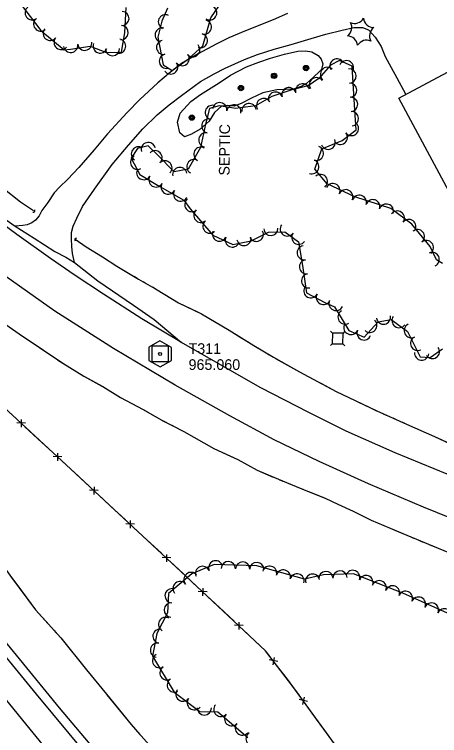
# Model space of a CAD drawing. Extents: x 353423 to 364002, y 127000 to 201942.
# Drawn here: x 358568 to 358806.9, y 133651.2 to 134056.7 of the extents above; entities that cross this region are included whole.
import ezdxf

# ---------------------------------------------------------------- set-up
doc = ezdxf.new("R2010")
doc.units = 0
for name, color, linetype in [('E_BMGRD', 7, 'Continuous'), ('E_DTM_SlopeBottom', 7, 'Continuous'), ('E_DTM_SlopeTop', 7, 'Continuous'), ('E_FEN_Generic', 7, 'Continuous'), ('E_MISCPROP', 7, 'Continuous'), ('E_SGN', 7, 'Continuous'), ('E_STRUCT_WingWall', 7, 'Continuous'), ('E_UTL_ETransformer', 7, 'Continuous'), ('E_WTR_FlowLine', 7, 'Continuous')]:
    doc.layers.add(name, color=color, linetype=linetype)

msp = doc.modelspace()

# ---------------------------------------------------------------- linework, layer by layer
at = {"layer": 'E_BMGRD'}
for points in [[(358643.46, 133869.57), (358643.46, 133862.18), (358649.92, 133858.46), (358656.31, 133862.12), (358656.31, 133869.45), (358649.79, 133873.17)], [(358645.37, 133861.31), (358645.37, 133870.31), (358654.37, 133870.31), (358654.37, 133861.31)]]:
    msp.add_lwpolyline(points, close=True, dxfattribs=at)
msp.add_circle((358649.87, 133865.81), 0.871, dxfattribs=at)
at = {"layer": 'E_DTM_SlopeBottom'}
for p, q in [((358571.92, 133824.67), (358572.02, 133828.9)), ((358574.25, 133826.94), (358569.32, 133827.08)), ((358594.71, 133808.03), (358589.78, 133808.17)), ((358592.38, 133805.76), (358592.48, 133809.99)), ((358615.13, 133789.07), (358610.2, 133789.23)), ((358612.8, 133786.81), (358612.91, 133791.04)), ((358633.19, 133767.83), (358633.3, 133772.06)), ((358635.52, 133770.09), (358630.59, 133770.25)), ((358655.92, 133751.11), (358650.99, 133751.27)), ((358653.59, 133748.85), (358653.7, 133753.08)), ((358676.28, 133732.08), (358671.35, 133732.26)), ((358673.94, 133729.83), (358674.07, 133734.06)), ((358694.26, 133710.77), (358694.39, 133715)), ((358696.6, 133713.02), (358691.67, 133713.2)), ((358713.34, 133690.93), (358714.16, 133695.07)), ((358716.02, 133692.76), (358711.18, 133693.74)), ((358732.73, 133670.42), (358727.93, 133671.53)), ((358730.01, 133668.66), (358730.94, 133672.78))]:
    msp.add_line(p, q, dxfattribs=at)
for points in [[(358836.43, 133525.4), (358796.03, 133580.43), (358760.79, 133628.75), (358724.55, 133678.75), (358709.17, 133698.85), (358664.38, 133740.86), (358599.77, 133800.98), (358519.01, 133875.61), (358455.91, 133934.64), (358435.86, 133952.59)], [(358569.08, 133829.34), (358560.77, 133837.02)], [(358581.23, 133818.11), (358573.92, 133824.87)], [(358589.54, 133810.43), (358581.23, 133818.11)], [(358601.69, 133799.2), (358599.77, 133800.98), (358594.38, 133805.96)], [(358609.97, 133791.49), (358601.69, 133799.2)], [(358622.08, 133780.22), (358614.79, 133787)], [(358630.37, 133772.51), (358622.08, 133780.22)], [(358642.48, 133761.24), (358635.19, 133768.02)], [(358650.76, 133753.53), (358642.48, 133761.24)], [(358662.87, 133742.26), (358655.58, 133749.04)], [(358671.13, 133734.52), (358664.38, 133740.86), (358662.87, 133742.26)], [(358683.2, 133723.21), (358675.93, 133730.02)], [(358691.45, 133715.46), (358683.2, 133723.21)], [(358703.52, 133704.15), (358696.26, 133710.96)], [(358711.34, 133696.01), (358709.17, 133698.85), (358703.52, 133704.15)], [(358721.39, 133682.88), (358715.34, 133690.78)], [(358728.14, 133673.79), (358724.55, 133678.75), (358721.39, 133682.88)], [(358737.85, 133660.4), (358732.01, 133668.46)], [(358744.49, 133651.23), (358737.85, 133660.4)]]:
    msp.add_lwpolyline(points, dxfattribs=at)
for centre, major_axis, ratio, start_param, end_param in [((358578.26, 133946.62), (1.1, -0.85), 0.731764, 5.356084, 7.210314), ((358603.23, 133929.74), (-1.27, 0.73), 0.674015, 5.356056, 7.210287)]:
    msp.add_ellipse(centre, major_axis=major_axis, ratio=ratio, start_param=start_param, end_param=end_param, dxfattribs=at)
at = {"layer": 'E_DTM_SlopeTop'}
for points in [[(358441.35, 134045.38), (358458.82, 134027.84), (358479.33, 134008.92), (358498.38, 133991.81), (358519.6, 133974.36), (358536.98, 133960.5), (358552.96, 133948.34), (358568.5, 133937.59), (358579.06, 133930.82), (358590.76, 133923.39), (358596.83, 133920.22), (358601.76, 133917.16), (358614.92, 133906.85), (358634.85, 133893.15), (358646.44, 133885.24), (358661.91, 133872.27)], [(358811.23, 133798.22), (358782.01, 133810.22), (358754.41, 133822.42), (358733.49, 133832.87), (358706.56, 133846.65), (358685.05, 133858.99), (358661.91, 133872.27), (358639.64, 133885.49), (358617.98, 133899.41), (358602.1, 133910), (358588.29, 133919.5), (358569.39, 133933.03), (358553.47, 133944.6), (358528.29, 133963.74), (358501.39, 133985.83), (358475.03, 134008.4), (358453.71, 134028.73), (358441, 134040.82)], [(358821.59, 133770.11), (358797.89, 133779.58), (358767.05, 133792.72), (358739.29, 133805.36), (358714.04, 133817.51), (358689, 133830.96), (358658.38, 133848.17), (358623.71, 133868.81), (358590.77, 133889.83), (358555.24, 133914.83), (358518.1, 133943.09), (358487.78, 133968.01), (358458.61, 133993.96), (358438.9, 134012.47)], [(358426.16, 133877.85), (358444.54, 133853.9), (358473.07, 133816.88), (358497.01, 133785.79), (358520.47, 133756.39), (358545.34, 133725.02), (358568.91, 133696.33), (358593.18, 133666.86), (358619.62, 133635.5), (358642.87, 133608.27), (358669.48, 133578.91), (358695.76, 133550.47), (358719.81, 133525.68)], [(358427.98, 133866.96), (358447.76, 133841.26), (358475.64, 133804.95), (358499.53, 133774.24), (358523.91, 133743.42), (358547.15, 133714.62), (358580.13, 133674.49), (358607.7, 133641.32), (358630.41, 133614.69), (358652.74, 133589.31), (358675.41, 133564.69), (358697.96, 133540.66), (358709.12, 133529.01)], [(358427.64, 133842.77), (358450.55, 133812.94), (358476.17, 133779.51), (358503.57, 133744.61), (358526.49, 133715.53), (358553.52, 133682.92), (358574.17, 133657.7), (358594.12, 133633.47), (358615.74, 133608.31), (358632.02, 133589.63), (358651.76, 133567.57), (358673.07, 133544.31), (358691.64, 133525.31)]]:
    msp.add_lwpolyline(points, dxfattribs=at)
at = {"layer": 'E_FEN_Generic'}
for points in [[(358568.39, 134066.85), (358582.85, 134047.75), (358595.93, 134036.77), (358599.52, 134037.17), (358610.55, 134038.88), (358619.81, 134035.34), (358628.08, 134035.48), (358630.04, 134046.33), (358630.85, 134060.61)], [(358654.07, 134060.2), (358650.78, 134053.02), (358648.58, 134043.93), (358651.61, 134028.38), (358656.7, 134025.27), (358665.74, 134031.84), (358673.79, 134039.08), (358678.35, 134054.76), (358685.24, 134065.18)], [(358808.53, 133916.57), (358805.2, 133918.67), (358801.72, 133926.29), (358791.4, 133938.77), (358779.49, 133947.5), (358759.3, 133954.09), (358743.71, 133961.49), (358736.89, 133969.79), (358740.77, 133981.14), (358752.23, 133985.77), (358760.02, 133991.92), (358759.22, 134002.87), (358758.36, 134017.99), (358757.81, 134027.6), (358750.64, 134030.88), (358745.61, 134028.14), (358739.07, 134020.65), (358733.04, 134016.66), (358723.26, 134014.11), (358712.72, 134010.64), (358703.43, 134005.24)], [(358703.43, 134005.24), (358692.15, 134003.86), (358683.05, 134005.31), (358677.62, 134003.75), (358675.33, 133995.07), (358672.53, 133981.96), (358665.72, 133969.79), (358657.69, 133968.23), (358648.37, 133977.71), (358643.21, 133982.9), (358637.11, 133981.25), (358633.58, 133975.92), (358638.39, 133966.71), (358648.31, 133960.75), (358663.15, 133952.26), (358666.81, 133947.49), (358679.45, 133932.57), (358690.79, 133927.44), (358701.07, 133929.32), (358710.7, 133934.21), (358719.97, 133934.52), (358727.72, 133928.89), (358729.93, 133915.6), (358732.21, 133900.22), (358742.38, 133894.76), (358747.97, 133892.23), (358755.94, 133878.92), (358764.61, 133875.3), (358772.41, 133883.88), (358779.77, 133885.19), (358788.93, 133878.47), (358795.98, 133864.24), (358801.58, 133863.72), (358808.61, 133868.63)], [(358814.72, 133718.47), (358786.36, 133731.35), (358758.59, 133742.23), (358741.63, 133741.54), (358731.01, 133739.15), (358704.31, 133746.68), (358680.34, 133747.44), (358667.79, 133742.14), (358654.55, 133731.16), (358654.01, 133720.3), (358647.96, 133708.63), (358645.65, 133695.85), (358657.78, 133675.6), (358672.19, 133664.69), (358682.38, 133664.57), (358699.12, 133650.06)]]:
    msp.add_lwpolyline(points, dxfattribs=at)
for centre, radius, start, end in [((358577.94, 134057.7), 4, 127.1526, 307.1373), ((358677.75, 134057.64), 4, 236.5384, 56.523), ((358628.4, 134054.46), 4, 266.7904, 86.7751), ((358652.86, 134052.54), 4, 65.4095, 245.3942), ((358582.77, 134051.33), 4, 127.1526, 307.1373), ((358674.69, 134049.65), 4, 253.7774, 73.762), ((358751.87, 134049.34), 5.72, 304.5822, 30.3471), ((358759.26, 134057.4), 5.72, 244.5822, 330.3471), ((358769.94, 134055.03), 5.72, 184.5822, 270.3471), ((358588.11, 134046.07), 4, 139.9618, 319.9465), ((358627.95, 134046.47), 4, 266.7904, 86.7751), ((358651.03, 134045.17), 4, 76.387, 256.3717), ((358773.23, 134044.59), 5.72, 124.5822, 210.3471), ((358594.23, 134040.93), 4, 139.9618, 319.9465), ((358626.56, 134038.85), 4, 259.7701, 79.7548), ((358672.45, 134041.97), 4, 253.7774, 73.762), ((358755.15, 134038.9), 5.72, 4.5822, 90.3471), ((358599.6, 134039.3), 4, 188.8427, 8.8274), ((358607.5, 134040.53), 4, 188.8427, 8.8274), ((358616.19, 134038.97), 4, 159.0777, 339.0623), ((358651.82, 134038.23), 4, 101.0539, 281.0386), ((358668.23, 134036.89), 4, 221.9877, 41.9724), ((358765.83, 134036.53), 5.72, 64.5822, 150.3471), ((358623.1, 134037.49), 4, 180.9606, 0.9452), ((358653.36, 134030.38), 4, 101.0539, 281.0386), ((358662.27, 134031.91), 4, 215.988, 35.9727), ((358749.25, 134027.75), 4, 28.614, 208.5987), ((358754.57, 134026.78), 4, 335.4095, 155.3942), ((358655.8, 134027.21), 4, 215.988, 35.9727), ((358743.91, 134023.01), 4, 48.8888, 228.8735), ((358756.03, 134022.09), 4, 273.2865, 93.2712), ((358737.69, 134017.22), 4, 33.4933, 213.478), ((358722.3, 134011.59), 4, 18.2382, 198.2229), ((358729.88, 134013.67), 4, 14.6432, 194.6278), ((358756.48, 134014.11), 4, 273.281, 93.2657), ((358714.7, 134009.08), 4, 18.2382, 198.2229), ((358683.43, 134003.13), 4, 350.9386, 170.9233), ((358699.85, 134002.69), 4, 6.9805, 186.9652), ((358708.06, 134005.51), 4, 30.1559, 210.1405), ((358756.94, 134006.12), 4, 273.281, 93.2657), ((358679.23, 134001.64), 4, 75.2497, 255.2343), ((358691.33, 134001.87), 4, 350.9386, 170.9233), ((358757.47, 133998.11), 4, 274.1685, 94.1532), ((358677.24, 133994), 4, 77.933, 257.9176), ((358757.43, 133992.55), 4, 218.3125, 38.2971), ((358675.57, 133986.17), 4, 77.933, 257.9176), ((358751.15, 133987.59), 4, 218.3125, 38.2971), ((358744.29, 133984.82), 4, 202.036, 22.0206), ((358637.65, 133978.28), 4, 56.5283, 236.513), ((358643.27, 133980.75), 4, 15.1247, 195.1094), ((358672.77, 133978.11), 4, 60.782, 240.7666), ((358737.7, 133978.64), 4, 251.1159, 71.1006), ((358647, 133976.12), 4, 314.5486, 134.5333), ((358637.19, 133973.54), 4, 117.6047, 297.5894), ((358652.61, 133970.41), 4, 314.5486, 134.5333), ((358668.86, 133971.13), 4, 60.782, 240.7666), ((358735.11, 133971.07), 4, 251.1159, 71.1006), ((358640.67, 133967.79), 4, 148.9813, 328.966), ((358660.92, 133966.73), 4, 10.9983, 190.983), ((358647.52, 133963.67), 4, 148.9813, 328.966), ((358739.94, 133962.77), 4, 309.4376, 129.4223), ((358654.4, 133959.68), 4, 150.232, 330.2166), ((358746.98, 133957.62), 4, 334.6021, 154.5868), ((358661.35, 133955.7), 4, 150.232, 330.2166), ((358754.21, 133954.19), 4, 334.6021, 154.5868), ((358761.84, 133951.06), 4, 341.9384, 161.923), ((358667.68, 133949.78), 4, 127.4689, 307.4535), ((358769.44, 133948.58), 4, 341.9384, 161.923), ((358777.05, 133946.1), 4, 341.9384, 161.923), ((358672.74, 133943.72), 4, 130.2983, 310.283), ((358783.18, 133942.2), 4, 323.7759, 143.7605), ((358789.64, 133937.47), 4, 323.7759, 143.7605), ((358677.91, 133937.62), 4, 130.2983, 310.283), ((358721.34, 133936.11), 4, 144.0331, 324.0178), ((358683.19, 133933.18), 4, 155.6456, 335.6303), ((358703.91, 133933.11), 4, 206.963, 26.9477), ((358712.08, 133936.35), 4, 181.867, 1.8517), ((358727.81, 133931.41), 4, 144.0331, 324.0178), ((358794.47, 133931.78), 4, 309.571, 129.5556), ((358690.47, 133929.88), 4, 155.6456, 335.6303), ((358697.01, 133930.7), 4, 190.3948, 10.3794), ((358799.56, 133925.61), 4, 309.571, 129.5556), ((358730.86, 133922.73), 4, 99.4408, 279.4254), ((358802.79, 133918.92), 4, 294.5784, 114.563), ((358732.16, 133914.8), 4, 98.4558, 278.4404), ((358733.34, 133906.89), 4, 98.4558, 278.4404), ((358734.59, 133901.32), 4, 151.7551, 331.7398), ((358741.63, 133897.54), 4, 151.7551, 331.7398), ((358748.73, 133894.18), 4, 155.6822, 335.6669), ((358753.82, 133886.54), 4, 120.9257, 300.9104), ((358767.76, 133881.87), 4, 227.724, 47.7086), ((358775.38, 133886.53), 4, 190.1081, 10.0928), ((358784.16, 133884.56), 4, 143.7759, 323.7605), ((358757.1, 133880.71), 4, 157.34, 337.3247), ((358791.05, 133878.91), 4, 116.3683, 296.353), ((358764.48, 133877.63), 4, 157.34, 337.3247), ((358794.6, 133871.74), 4, 116.3683, 296.353), ((358802.88, 133867.19), 4, 214.8867, 34.8714), ((358796.84, 133866.27), 4, 174.6859, 354.6706), ((358681.1, 133745.49), 4, 22.9096, 202.8942), ((358688.21, 133745.09), 4, 358.2065, 178.1912), ((358696.21, 133744.84), 4, 358.2065, 178.1912), ((358704.2, 133744.59), 4, 358.2065, 178.1912), ((358667.26, 133738.97), 4, 39.6801, 219.6647), ((358673.73, 133742.37), 4, 22.9096, 202.8942), ((358711.4, 133742.51), 4, 344.2607, 164.2453), ((358719.1, 133740.34), 4, 344.2607, 164.2453), ((358743.04, 133739.5), 4, 2.3418, 182.3265), ((358751.03, 133739.83), 4, 2.3418, 182.3265), ((358758.15, 133740.15), 4, 338.6275, 158.6122), ((358726.8, 133738.17), 4, 344.2607, 164.2453), ((358735.58, 133738.03), 4, 12.666, 192.6507), ((358765.6, 133737.23), 4, 338.6275, 158.6122), ((358661.1, 133733.87), 4, 39.6801, 219.6647), ((358773.05, 133734.32), 4, 338.6275, 158.6122), ((358780.5, 133731.4), 4, 338.6275, 158.6122), ((358656.58, 133729.83), 4, 87.1607, 267.1454), ((358787.79, 133728.4), 4, 335.5755, 155.5602), ((358795.08, 133725.1), 4, 335.5755, 155.5602), ((358656.18, 133721.84), 4, 87.1607, 267.1454), ((358802.36, 133721.79), 4, 335.5755, 155.5602), ((358809.64, 133718.48), 4, 335.5755, 155.5602), ((358652.94, 133713.69), 4, 62.5871, 242.5718), ((358649.8, 133707.07), 4, 79.7952, 259.7799), ((358648.38, 133699.2), 4, 79.7952, 259.7799), ((358649.62, 133693.3), 4, 120.9061, 300.8907), ((358653.73, 133686.44), 4, 120.9061, 300.8907), ((358657.84, 133679.58), 4, 120.9061, 300.8907), ((358662.72, 133674.48), 4, 142.8804, 322.8651), ((358669.1, 133669.65), 4, 142.8804, 322.8651), ((358674.75, 133666.75), 4, 179.3336, 359.3183), ((358684.01, 133665.92), 4, 139.0848, 319.0694), ((358690.05, 133660.68), 4, 139.0848, 319.0694), ((358696.1, 133655.44), 4, 139.0848, 319.0694), ((358702.08, 133649.41), 4, 124.0296, 304.0143)]:
    msp.add_arc(centre, radius, start, end, dxfattribs=at)
at = {"layer": 'E_MISCPROP'}
for points in [[(358721.46, 134057.17), (358713.36, 134053.61), (358697.86, 134047.58), (358688.4, 134043.65), (358681.33, 134040.1), (358671.27, 134034.54), (358661.85, 134029.09), (358655.76, 134024.28), (358648.51, 134018.28), (358638.54, 134008.92), (358631.3, 134001.51), (358620.34, 133989.49), (358612.82, 133980.62), (358604.2, 133970.66), (358597.99, 133964.06), (358593.36, 133959.62), (358590.36, 133956.43), (358586.81, 133950.96), (358583.43, 133946.41), (358581.95, 133943.54), (358579.93, 133941.1), (358577.81, 133939.53), (358575.09, 133938.35), (358572.7, 133937.98), (358568.5, 133937.59)], [(358601.76, 133917.16), (358600.59, 133922.27), (358600.17, 133926.18), (358600.02, 133930.74), (358600.09, 133934.16), (358600.97, 133937.74), (358602.99, 133942.24), (358606.33, 133948.8), (358612.99, 133958.49), (358622.92, 133972.25), (358632.13, 133983.24), (358640.2, 133992.33), (358648.21, 134000.23), (358655.02, 134005.96), (358661.98, 134011.09), (358672.66, 134018.98), (358680.22, 134023.35), (358686.47, 134026.48), (358697.24, 134031.44), (358704.53, 134034.13), (358713.88, 134037.13), (358723.49, 134039.76), (358734.8, 134043.14), (358742.95, 134045.72), (358752.19, 134047.86), (358758.71, 134049.46), (358763.6, 134049.44), (358767.07, 134048.02), (358770.8, 134043.88), (358774.15, 134038.77), (358776.41, 134033.06), (358779.81, 134026.8), (358782.94, 134021.03), (358787.99, 134011.7)]]:
    msp.add_lwpolyline(points, dxfattribs=at)
at = {"layer": 'E_SGN'}
for p, q in [((358746.7, 133877.54), (358745.65, 133878.61)), ((358753.77, 133878.53), (358752.7, 133877.48)), ((358746.63, 133871.54), (358745.56, 133870.49)), ((358753.68, 133870.4), (358752.63, 133871.48))]:
    msp.add_line(p, q, dxfattribs=at)
msp.add_lwpolyline([(358752.63, 133871.48), (358752.7, 133877.48), (358746.7, 133877.54), (358746.63, 133871.54)], close=True, dxfattribs=at)
at = {"layer": 'E_STRUCT_WingWall'}
for points in [[(358534.94, 133987.85), (358543.69, 133976.85), (358550.45, 133968.09), (358561.49, 133959.14), (358571.4, 133951.29), (358578.66, 133946.38)], [(358570.63, 133951.9), (358571.4, 133951.29), (358578.66, 133946.38)], [(358434.66, 133934.63), (358451.45, 133909.81), (358469.22, 133881.46), (358483.15, 133860.56), (358497.03, 133840.37), (358514.86, 133815.28), (358528.47, 133795.25), (358541.86, 133774.08), (358554.5, 133756.39), (358566.33, 133740.17), (358579.9, 133721.98), (358594.01, 133706.24), (358608.44, 133688.22), (358619.8, 133674.44), (358633.53, 133657.4), (358647.75, 133641.22), (358663.32, 133622.65), (358680.03, 133604.95), (358694.85, 133588.44), (358708.69, 133572.7), (358723.73, 133555), (358737.03, 133540.13), (358750.67, 133524.94)], [(358602.22, 133930.27), (358608.34, 133926.07), (358617.44, 133920.34), (358625.51, 133915.15), (358637.81, 133907.94), (358648.21, 133901.93), (358660.13, 133894.61), (358673.09, 133888.43), (358688.64, 133879.2), (358702.61, 133870.52), (358713.61, 133863.91), (358728.14, 133855.77), (358738.38, 133850.3), (358748.78, 133844.73), (358759.46, 133839.53), (358771.66, 133833.73), (358788.3, 133826.4), (358804.13, 133819.34), (358821.36, 133811.56)], [(358602.22, 133930.27), (358608.34, 133926.07), (358617.44, 133920.34), (358625.51, 133915.15), (358626.57, 133914.53)], [(358630.02, 133912.51), (358631.74, 133911.5)], [(358635.2, 133909.48), (358636.92, 133908.46)], [(358640.38, 133906.46), (358642.11, 133905.46)], [(358645.58, 133903.46), (358648.21, 133901.93), (358660.13, 133894.61), (358670.93, 133889.46)], [(358550.29, 133891.45), (358557.37, 133886.28), (358570.58, 133877.11), (358574.04, 133874.81)], [(358670.93, 133889.46), (358673.09, 133888.43), (358688.64, 133879.2), (358695.88, 133874.7)], [(358557.37, 133886.28), (358570.58, 133877.11), (358584.4, 133867.89), (358595.17, 133860.57), (358607.09, 133853.26), (358617.66, 133847.46), (358627.68, 133841.29), (358640.31, 133834.51), (358650.44, 133828.78), (358663.29, 133822.16), (358680.03, 133812.71), (358693.64, 133806.42), (358704.42, 133800.51), (358714.07, 133796.24), (358723.23, 133792.57), (358732.77, 133788.68), (358742.7, 133784.63), (358749.8, 133781.24), (358758.36, 133777.3), (358768.44, 133772.32), (358779.18, 133767.83), (358788.5, 133763.83), (358806.07, 133756.5), (358814.69, 133753.1)], [(358577.36, 133872.58), (358579.03, 133871.47)], [(358699.28, 133872.59), (358700.98, 133871.53)], [(358582.35, 133869.25), (358584.02, 133868.14)], [(358704.39, 133869.45), (358706.11, 133868.42)], [(358587.33, 133865.9), (358588.98, 133864.77)], [(358709.54, 133866.36), (358711.25, 133865.33)], [(358592.29, 133862.53), (358595.17, 133860.57), (358607.09, 133853.26), (358617.2, 133847.71)], [(358714.7, 133863.3), (358728.14, 133855.77), (358738.38, 133850.3), (358740.13, 133849.36)], [(358740.13, 133849.36), (358748.78, 133844.73), (358759.46, 133839.53), (358766.06, 133836.39)], [(358617.2, 133847.71), (358617.66, 133847.46), (358627.68, 133841.29), (358640.31, 133834.51), (358642.38, 133833.34)], [(358769.67, 133834.67), (358771.48, 133833.82)], [(358775.14, 133832.2), (358776.97, 133831.39)], [(358645.86, 133831.37), (358647.6, 133830.39)], [(358651.1, 133828.44), (358652.87, 133827.52)], [(358780.63, 133829.78), (358782.46, 133828.97)], [(358656.43, 133825.69), (358658.21, 133824.78)], [(358786.12, 133827.36), (358788.3, 133826.4), (358804.13, 133819.34), (358812.59, 133815.52)], [(358661.76, 133822.95), (358663.29, 133822.16), (358680.03, 133812.71), (358687.35, 133809.33)], [(358687.35, 133809.33), (358693.64, 133806.42), (358704.42, 133800.51), (358713.36, 133796.56)], [(358717.06, 133795.04), (358718.92, 133794.3)], [(358722.63, 133792.81), (358723.23, 133792.57), (358724.48, 133792.06)], [(358728.19, 133790.55), (358730.04, 133789.8)], [(358733.74, 133788.29), (358742.7, 133784.63), (358749.8, 133781.24), (358758.36, 133777.3), (358760.18, 133776.4)], [(358760.18, 133776.4), (358768.44, 133772.32), (358779.18, 133767.83), (358786.67, 133764.62)], [(358790.36, 133763.06), (358792.2, 133762.29)], [(358552.27, 133759.51), (358554.5, 133756.39), (358566.33, 133740.17), (358569.37, 133736.09)], [(358795.89, 133760.75), (358797.74, 133759.98)], [(358801.43, 133758.43), (358803.28, 133757.66)], [(358569.37, 133736.09), (358579.9, 133721.98), (358587.51, 133713.49)], [(358590.18, 133710.52), (358591.51, 133709.03)], [(358594.17, 133706.04), (358595.42, 133704.48)], [(358597.92, 133701.36), (358599.17, 133699.79)], [(358601.67, 133696.67), (358608.44, 133688.22), (358619.8, 133674.44), (358619.99, 133674.19)], [(358619.99, 133674.19), (358633.53, 133657.4), (358638.43, 133651.82)]]:
    msp.add_lwpolyline(points, dxfattribs=at)
at = {"layer": 'E_UTL_ETransformer'}
for centre, radius in [((358731.87, 134026.57), 1.5), ((358731.87, 134026.57), 1.22), ((358731.89, 134026.57), 0.968), ((358731.89, 134026.54), 0.605), ((358713.88, 134022.18), 1.5), ((358713.89, 134022.18), 1.22), ((358713.9, 134022.18), 0.968), ((358713.91, 134022.15), 0.605), ((358695.29, 134015.35), 1.5), ((358695.29, 134015.36), 1.22), ((358695.31, 134015.35), 0.968), ((358695.31, 134015.32), 0.605), ((358667.7, 133998.73), 1.5), ((358667.71, 133998.73), 1.22), ((358667.72, 133998.72), 0.968), ((358667.73, 133998.7), 0.605)]:
    msp.add_circle(centre, radius, dxfattribs=at)
at = {"layer": 'E_WTR_FlowLine'}
for points in [[(358736.32, 134021.66), (358732.07, 134017.93), (358729.19, 134016.2), (358724.84, 134014.75), (358720.55, 134014.49), (358715.5, 134014.4), (358707.67, 134012.64), (358701.2, 134009.57), (358695.38, 134006.65), (358691.52, 134005.2), (358687.83, 134005.54), (358684.35, 134005.23), (358680.49, 134001.66), (358677.38, 133996.62), (358672.47, 133992.24), (358667.58, 133989.38), (358663.61, 133987.82), (358660.9, 133990.16), (358659.56, 133996.2), (358661.05, 134001.18), (358667.21, 134007.84), (358672.65, 134011.79), (358682.99, 134018.26), (358689.41, 134022.64), (358698.39, 134027.28), (358705.35, 134029.91), (358711.82, 134032.22), (358719.8, 134034.42), (358727.36, 134036.02), (358731.59, 134036.23), (358735.23, 134035.67), (358738.64, 134033.65), (358740.43, 134031.63), (358741.4, 134028.86), (358740.57, 134025.82), (358739.32, 134024.36)], [(358812.2, 133957.3), (358784.05, 134009.58), (358825.05, 134031.66), (358853.2, 133979.38)]]:
    msp.add_lwpolyline(points, close=True, dxfattribs=at)

# ---------------------------------------------------------------- texts
at = {"layer": 'E_BMGRD'}
for s, p in [('T311', (358665.87, 133865.81)), ('965.060', (358665.87, 133856.81))]:
    msp.add_text(s, height=6, dxfattribs=at).set_placement(p)
at = {"layer": 'E_UTL_ETransformer'}
msp.add_text('SEPTIC', height=6, rotation=89.3709, dxfattribs=at).set_placement((358688.88, 133966.08))

doc.saveas('drawing.dxf')
